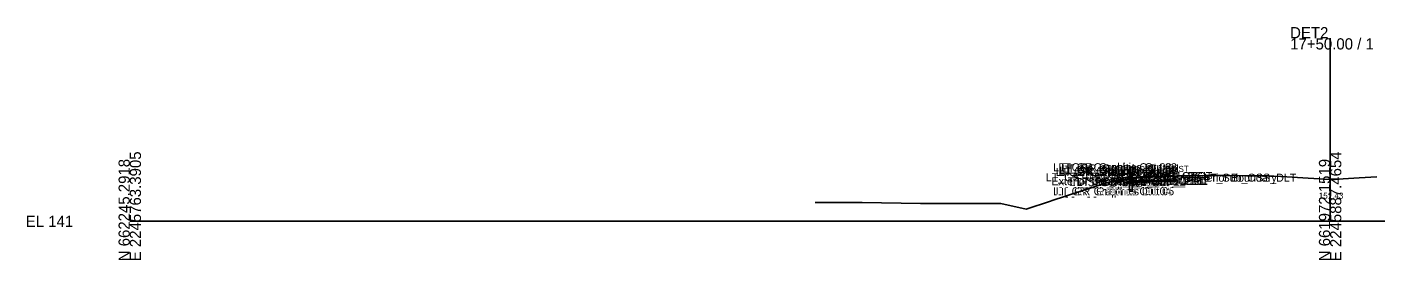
# Model space of a CAD drawing. Extents: x -26 to 603, y -10 to 9526.
# Drawn here: x -25.7 to 311.2, y 490.3 to 548.6 of the extents above; entities that cross this region are included whole.
import ezdxf

# ---------------------------------------------------------------- set-up
doc = ezdxf.new("R2010")
doc.units = 0
for name, color, linetype in [('Default', 7, 'Continuous'), ('Exist Cross Section Cell', 7, 'Continuous'), ('Exist XS Center Line Elevation Label', 7, 'Continuous'), ('Exist XS Ground Line', 7, 'Continuous'), ('Prop CMT Guardrail Graphics', 7, 'Continuous'), ('Prop CMT Pvmt Course 1', 7, 'Continuous'), ('Prop CMT Pvmt Course 3', 7, 'Continuous'), ('Prop CMT Pvmt Surface', 7, 'Continuous'), ('Prop CMT Pvmt Surface Shoulder', 7, 'Continuous'), ('Prop CMT Shld Paved Course 1', 7, 'Continuous'), ('Prop CMT Shld Paved Course 2', 7, 'Continuous'), ('Prop CMT Shld Paved Course 3', 7, 'Continuous'), ('Prop CMT Slope Grass', 7, 'Continuous'), ('Prop CMT Subgrade Earthwork', 7, 'Continuous'), ('Prop XS SE Text', 7, 'Continuous'), ('Prop XS Side Slope Text', 7, 'Continuous'), ('Scratch_Level_2', 7, 'Continuous')]:
    doc.layers.add(name, color=color, linetype=linetype)

msp = doc.modelspace()

# ---------------------------------------------------------------- linework, layer by layer
at = {"layer": 'Exist Cross Section Cell'}
for p, q in [((300, 500), (300, 545.79)), ((0, 500), (300, 500)), ((300, 500), (600, 500))]:
    msp.add_line(p, q, dxfattribs=at)
at = {"layer": 'Exist XS Ground Line'}
for p, q in [((230.52, 505.21), (244.39, 509.72)), ((244.39, 509.72), (245.44, 509.9)), ((245.44, 509.9), (247.8, 510.27)), ((247.8, 510.27), (252.26, 511.04)), ((252.26, 511.04), (252.59, 511.04)), ((252.59, 511.04), (253.34, 511.01)), ((253.34, 511.01), (257.77, 511.18)), ((257.77, 511.18), (258.6, 511.15)), ((258.6, 511.15), (258.89, 511.26)), ((258.89, 511.26), (260.69, 511.31)), ((260.69, 511.31), (261.45, 511.33)), ((261.45, 511.33), (262, 511.33)), ((262, 511.33), (262.78, 511.34)), ((262.78, 511.34), (263.92, 511.36)), ((263.92, 511.36), (269.04, 511.43)), ((269.04, 511.43), (269.55, 511.43)), ((269.55, 511.43), (271.73, 511.47)), ((271.73, 511.47), (272.22, 511.48)), ((272.22, 511.48), (273.68, 511.53)), ((273.68, 511.53), (274.24, 511.49)), ((274.24, 511.49), (274.91, 511.48)), ((274.91, 511.48), (279.1, 511.41)), ((279.1, 511.41), (280.4, 511.39)), ((280.4, 511.39), (280.88, 511.38)), ((280.88, 511.38), (283.82, 511.35)), ((283.82, 511.35), (284.48, 511.36)), ((284.48, 511.36), (285.07, 511.31)), ((285.07, 511.31), (285.89, 511.28)), ((285.89, 511.28), (287.64, 511.22)), ((287.64, 511.22), (289.22, 511.09)), ((289.22, 511.09), (294.52, 510.81)), ((294.52, 510.81), (297.34, 510.65)), ((297.34, 510.65), (298.31, 510.56)), ((298.31, 510.56), (300, 510.43)), ((300, 510.43), (300.35, 510.4)), ((300.35, 510.4), (301.3, 510.48)), ((301.3, 510.48), (303.27, 510.62)), ((303.27, 510.62), (307.27, 510.85)), ((307.27, 510.85), (311.71, 511.1)), ((171.3, 504.7), (183.01, 504.68)), ((183.01, 504.68), (197.62, 504.45)), ((197.62, 504.45), (217.27, 504.44)), ((217.27, 504.44), (217.67, 504.45)), ((217.67, 504.45), (224.06, 503.08)), ((224.06, 503.08), (230.13, 505.08)), ((230.13, 505.08), (230.52, 505.21))]:
    msp.add_line(p, q, dxfattribs=at)
at = {"layer": 'Prop CMT Guardrail Graphics'}
for points in [[(249.88, 507.58), (249.88, 513.58)], [(249.88, 513.58), (251.21, 513.58), (251.48, 513.29)], [(251.48, 512.71), (251.21, 512.42), (250.54, 512.42)], [(250.54, 512.42), (250.54, 507.58)], [(251.48, 513.29), (251.21, 513)], [(251.21, 513), (251.48, 512.71)], [(250.54, 507.58), (249.88, 507.58)]]:
    msp.add_lwpolyline(points, dxfattribs=at)
at = {"layer": 'Prop CMT Pvmt Course 1'}
for points in [[(261.45, 511.33), (261.08, 511.32)], [(261.08, 511.32), (261.08, 510.41)], [(261.08, 510.41), (261.45, 510.42)], [(261.45, 510.42), (261.45, 511.33)]]:
    msp.add_lwpolyline(points, dxfattribs=at)
at = {"layer": 'Prop CMT Pvmt Course 3'}
for points in [[(261.45, 510.08), (261.08, 510.08)], [(261.08, 510.08), (261.08, 510.08)], [(261.08, 510.08), (261.45, 510.08)], [(261.45, 510.08), (261.45, 510.08)]]:
    msp.add_lwpolyline(points, dxfattribs=at)
at = {"layer": 'Prop CMT Pvmt Surface'}
msp.add_lwpolyline([(261.45, 511.33), (261.08, 511.32)], dxfattribs=at)
at = {"layer": 'Prop CMT Pvmt Surface Shoulder'}
msp.add_lwpolyline([(261.08, 511.32), (251.48, 511.08)], dxfattribs=at)
at = {"layer": 'Prop CMT Shld Paved Course 1'}
for p, q in [((251.48, 511.08), (250.54, 510.14)), ((261.08, 511.32), (252.41, 511.11))]:
    msp.add_line(p, q, dxfattribs=at)
for points in [[(251.47, 510.17), (261.08, 510.41)], [(261.08, 510.41), (261.08, 511.32)]]:
    msp.add_lwpolyline(points, dxfattribs=at)
at = {"layer": 'Prop CMT Shld Paved Course 2'}
for p, q in [((250.54, 510.14), (250.22, 509.83)), ((261.08, 510.41), (250.54, 510.14))]:
    msp.add_line(p, q, dxfattribs=at)
for points in [[(251.13, 509.83), (261.08, 510.08)], [(261.08, 510.08), (261.08, 510.41)]]:
    msp.add_lwpolyline(points, dxfattribs=at)
at = {"layer": 'Prop CMT Shld Paved Course 3'}
for points in [[(261.08, 510.08), (251.13, 509.83), (250.63, 509.81)], [(250.63, 509.81), (261.08, 510.08)], [(250.63, 509.81), (250.63, 509.81)], [(261.08, 510.08), (261.08, 510.08)]]:
    msp.add_lwpolyline(points, dxfattribs=at)
at = {"layer": 'Prop CMT Slope Grass'}
for points in [[(248.48, 510.84), (245.82, 509.96)], [(251.48, 511.08), (248.48, 510.84)]]:
    msp.add_lwpolyline(points, dxfattribs=at)
at = {"layer": 'Prop CMT Subgrade Earthwork'}
msp.add_line((261.45, 510.08), (261.45, 510.42), dxfattribs=at)
for points in [[(250.63, 509.81), (245.82, 509.96)], [(261.08, 510.08), (250.63, 509.81)], [(261.45, 510.08), (261.08, 510.08)]]:
    msp.add_lwpolyline(points, dxfattribs=at)

# ---------------------------------------------------------------- texts
at = {"layer": 'Default'}
msp.add_text('-', height=0.0001, dxfattribs=at).set_placement((0, 500))
msp.add_text('-', height=0.0001, dxfattribs=at).set_placement((0, 500))
msp.add_text('-', height=0.0001, dxfattribs=at).set_placement((0, 500))
msp.add_text('-', height=0.0001, dxfattribs=at).set_placement((0, 500))
msp.add_text('-', height=0.0001, dxfattribs=at).set_placement((0, 500))
at = {"layer": 'Exist Cross Section Cell'}
for s, p in [('17+50.00 / 1', (290, 542.99)), ('DET2', (290, 545.79)), ('EL 141', (-26, 498.6))]:
    msp.add_text(s, height=2.8, dxfattribs=at).set_placement(p)
for s, p in [('E 2245763.3905', (2.8, 490)), ('E 2245887.4654', (302.8, 490)), ('N 662245.2918', (0, 490)), ('N 661972.1519', (300, 490))]:
    msp.add_text(s, height=2.8, rotation=90, dxfattribs=at).set_placement(p)
at = {"layer": 'Exist XS Center Line Elevation Label'}
msp.add_text('151.43', height=1.5, dxfattribs=at).set_placement((297.17, 505.68))
at = {"layer": 'Prop XS SE Text'}
msp.add_text('EXIST', height=1.5, rotation=1.4321, dxfattribs=at).set_placement((258.89, 512.27))
at = {"layer": 'Prop XS Side Slope Text'}
msp.add_text('3:1', height=1.5, rotation=18.4332, dxfattribs=at).set_placement((245.42, 510.57))
at = {"layer": 'Scratch_Level_2'}
for s, p in [('LT_GS_OS_GR_Face_Graphics', (228.94, 510.03)), ('LT_GR_Graphics Out 03', (230.78, 512.53)), ('LT_GR_Graphics Out 06', (231.4, 511.37)), ('LT_GR_Graphics Out 02', (232.11, 512.53)), ('LT_GR_Graphics Out 09', (232.11, 511.95)), ('LT_GR_Graphics Out 07', (232.11, 511.37)), ('LT_GR_Graphics Out 08', (232.38, 511.66)), ('LT_GR_Graphics Out 01', (232.95, 512.24)), ('LT_PS1_OEOP', (243.21, 510.11)), ('LT_PV1_OEOT', (251.82, 510.32)), ('LT_PV1_PGL', (253.23, 510.33)), ('Exterior Boundary', (230.37, 509.04)), ('LT_Sub_Trench_Out', (234.83, 508.81)), ('LT_PS3_Shelf_Out', (236.61, 508.81)), ('LT_Slope_Fill', (236.75, 509.04)), ('LT_GS_OS_CTL', (237.85, 509.79)), ('LT_PS3_OEOP', (241.36, 508.83)), ('LT_PS2_OEOP', (241.71, 509.17)), ('LT_Sub_OEOT', (251.16, 509.08)), ('LT_PV2_OEOT', (251.26, 509.41)), ('LT_PV3_OEOT', (251.26, 509.08)), ('LT_Sub_PGL', (252.57, 509.08)), ('LT_PV2_PGL', (252.66, 509.42)), ('LT_PV3_PGL', (252.66, 509.08)), ('Exterior Boundary', (265.25, 509.92)), ('LT_Sub_OSS_DLT', (268.51, 509.92)), ('LT_GR_Graphics Out 04', (230.78, 506.53)), ('LT_GR_Graphics Out 05', (231.44, 506.53))]:
    msp.add_text(s, height=2, dxfattribs=at).set_placement(p)

doc.saveas('drawing.dxf')
